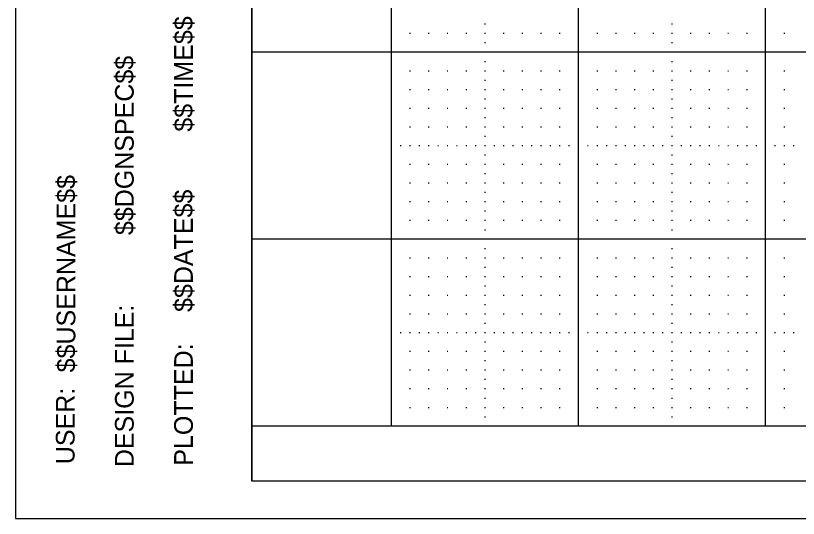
# Model space of a CAD drawing. Extents: x -1.3 to 32.1, y -0.2 to 20.7.
# Drawn here: x -1.263 to 2.92, y -0.2 to 2.487 of the extents above; entities that cross this region are included whole.
import ezdxf

# ---------------------------------------------------------------- set-up
doc = ezdxf.new("R2010")
doc.units = 0
for name, color, linetype in [('Level 1', 7, 'Continuous'), ('Level 37', 7, 'Continuous'), ('Level 5', 7, 'Continuous'), ('Level 6', 7, 'Continuous'), ('Level 62', 7, 'Continuous'), ('Level 63', 7, 'Continuous')]:
    doc.layers.add(name, color=color, linetype=linetype)

msp = doc.modelspace()

# ---------------------------------------------------------------- linework, layer by layer
at = {"layer": 'Level 1'}
for p, q in [((-0.001, -0.001), (-0.001, 20.545)), ((31.617, -0.001), (-0.001, -0.001))]:
    msp.add_line(p, q, dxfattribs=at)
at = {"layer": 'Level 37'}
for p, q in [((-0.001, 0.4818), (-0.001, 10.272)), ((-0.001, -0.001), (-0.001, 0.4818)), ((-0.001, 0.4818), (-0.001, 0.4818)), ((31.618, -0.001), (-0.001, -0.001))]:
    msp.add_line(p, q, dxfattribs=at)
at = {"layer": 'Level 5'}
for p, q in [((1.2425, 2.443), (1.2475, 2.443)), ((2.2425, 2.443), (2.2475, 2.443)), ((0.8425, 2.393), (0.8475, 2.393)), ((0.9425, 2.393), (0.9475, 2.393)), ((1.0425, 2.393), (1.0475, 2.393)), ((1.1425, 2.393), (1.1475, 2.393)), ((1.2425, 2.393), (1.2475, 2.393)), ((1.3425, 2.393), (1.3475, 2.393)), ((1.4425, 2.393), (1.4475, 2.393)), ((1.5425, 2.393), (1.5475, 2.393)), ((1.6425, 2.393), (1.6475, 2.393)), ((1.8425, 2.393), (1.8475, 2.393)), ((1.9425, 2.393), (1.9475, 2.393)), ((2.0425, 2.393), (2.0475, 2.393)), ((2.1425, 2.393), (2.1475, 2.393)), ((2.2425, 2.393), (2.2475, 2.393)), ((2.3425, 2.393), (2.3475, 2.393)), ((2.4425, 2.393), (2.4475, 2.393)), ((2.5425, 2.393), (2.5475, 2.393)), ((2.6425, 2.393), (2.6475, 2.393)), ((2.8425, 2.393), (2.8475, 2.393)), ((1.2425, 2.343), (1.2475, 2.343)), ((2.2425, 2.343), (2.2475, 2.343)), ((1.2425, 2.243), (1.2475, 2.243)), ((2.2425, 2.243), (2.2475, 2.243)), ((0.8425, 2.193), (0.8475, 2.193)), ((0.9425, 2.193), (0.9475, 2.193)), ((1.0425, 2.193), (1.0475, 2.193)), ((1.1425, 2.193), (1.1475, 2.193)), ((1.2425, 2.193), (1.2475, 2.193)), ((1.3425, 2.193), (1.3475, 2.193)), ((1.4425, 2.193), (1.4475, 2.193)), ((1.5425, 2.193), (1.5475, 2.193)), ((1.6425, 2.193), (1.6475, 2.193)), ((1.8425, 2.193), (1.8475, 2.193)), ((1.9425, 2.193), (1.9475, 2.193)), ((2.0425, 2.193), (2.0475, 2.193)), ((2.1425, 2.193), (2.1475, 2.193)), ((2.2425, 2.193), (2.2475, 2.193)), ((2.3425, 2.193), (2.3475, 2.193)), ((2.4425, 2.193), (2.4475, 2.193)), ((2.5425, 2.193), (2.5475, 2.193)), ((2.6425, 2.193), (2.6475, 2.193)), ((2.8425, 2.193), (2.8475, 2.193)), ((1.2425, 2.143), (1.2475, 2.143)), ((2.2425, 2.143), (2.2475, 2.143)), ((0.8425, 2.093), (0.8475, 2.093)), ((0.9425, 2.093), (0.9475, 2.093)), ((1.0425, 2.093), (1.0475, 2.093)), ((1.1425, 2.093), (1.1475, 2.093)), ((1.2425, 2.093), (1.2475, 2.093)), ((1.3425, 2.093), (1.3475, 2.093)), ((1.4425, 2.093), (1.4475, 2.093)), ((1.5425, 2.093), (1.5475, 2.093)), ((1.6425, 2.093), (1.6475, 2.093)), ((1.8425, 2.093), (1.8475, 2.093)), ((1.9425, 2.093), (1.9475, 2.093)), ((2.0425, 2.093), (2.0475, 2.093)), ((2.1425, 2.093), (2.1475, 2.093)), ((2.2425, 2.093), (2.2475, 2.093)), ((2.3425, 2.093), (2.3475, 2.093)), ((2.4425, 2.093), (2.4475, 2.093)), ((2.5425, 2.093), (2.5475, 2.093)), ((2.6425, 2.093), (2.6475, 2.093)), ((2.8425, 2.093), (2.8475, 2.093)), ((1.2425, 2.043), (1.2475, 2.043)), ((2.2425, 2.043), (2.2475, 2.043)), ((0.8425, 1.993), (0.8475, 1.993)), ((0.9425, 1.993), (0.9475, 1.993)), ((1.0425, 1.993), (1.0475, 1.993)), ((1.1425, 1.993), (1.1475, 1.993)), ((1.2425, 1.993), (1.2475, 1.993)), ((1.3425, 1.993), (1.3475, 1.993)), ((1.4425, 1.993), (1.4475, 1.993)), ((1.5425, 1.993), (1.5475, 1.993)), ((1.6425, 1.993), (1.6475, 1.993)), ((1.8425, 1.993), (1.8475, 1.993)), ((1.9425, 1.993), (1.9475, 1.993)), ((2.0425, 1.993), (2.0475, 1.993)), ((2.1425, 1.993), (2.1475, 1.993)), ((2.2425, 1.993), (2.2475, 1.993)), ((2.3425, 1.993), (2.3475, 1.993)), ((2.4425, 1.993), (2.4475, 1.993)), ((2.5425, 1.993), (2.5475, 1.993)), ((2.6425, 1.993), (2.6475, 1.993)), ((2.8425, 1.993), (2.8475, 1.993)), ((1.2425, 1.943), (1.2475, 1.943)), ((2.2425, 1.943), (2.2475, 1.943)), ((0.8425, 1.893), (0.8475, 1.893)), ((0.9425, 1.893), (0.9475, 1.893)), ((1.0425, 1.893), (1.0475, 1.893)), ((1.1425, 1.893), (1.1475, 1.893)), ((1.2425, 1.893), (1.2475, 1.893)), ((1.3425, 1.893), (1.3475, 1.893)), ((1.4425, 1.893), (1.4475, 1.893)), ((1.5425, 1.893), (1.5475, 1.893)), ((1.6425, 1.893), (1.6475, 1.893)), ((1.8425, 1.893), (1.8475, 1.893)), ((1.9425, 1.893), (1.9475, 1.893)), ((2.0425, 1.893), (2.0475, 1.893)), ((2.1425, 1.893), (2.1475, 1.893)), ((2.2425, 1.893), (2.2475, 1.893)), ((2.3425, 1.893), (2.3475, 1.893)), ((2.4425, 1.893), (2.4475, 1.893)), ((2.5425, 1.893), (2.5475, 1.893)), ((2.6425, 1.893), (2.6475, 1.893)), ((2.8425, 1.893), (2.8475, 1.893)), ((1.2425, 1.843), (1.2475, 1.843)), ((2.2425, 1.843), (2.2475, 1.843)), ((0.7925, 1.793), (0.7975, 1.793)), ((0.8425, 1.793), (0.8475, 1.793)), ((0.8925, 1.793), (0.8975, 1.793)), ((0.9425, 1.793), (0.9475, 1.793)), ((0.9925, 1.793), (0.9975, 1.793)), ((1.0425, 1.793), (1.0475, 1.793)), ((1.0925, 1.793), (1.0975, 1.793)), ((1.1425, 1.793), (1.1475, 1.793)), ((1.1925, 1.793), (1.1975, 1.793)), ((1.2425, 1.793), (1.2475, 1.793)), ((1.2925, 1.793), (1.2975, 1.793)), ((1.3425, 1.793), (1.3475, 1.793)), ((1.3925, 1.793), (1.3975, 1.793)), ((1.4425, 1.793), (1.4475, 1.793)), ((1.4925, 1.793), (1.4975, 1.793)), ((1.5425, 1.793), (1.5475, 1.793)), ((1.5925, 1.793), (1.5975, 1.793)), ((1.6425, 1.793), (1.6475, 1.793)), ((1.6925, 1.793), (1.6975, 1.793)), ((1.7925, 1.793), (1.7975, 1.793)), ((1.8425, 1.793), (1.8475, 1.793)), ((1.8925, 1.793), (1.8975, 1.793)), ((1.9425, 1.793), (1.9475, 1.793)), ((1.9925, 1.793), (1.9975, 1.793)), ((2.0425, 1.793), (2.0475, 1.793)), ((2.0925, 1.793), (2.0975, 1.793)), ((2.1425, 1.793), (2.1475, 1.793)), ((2.1925, 1.793), (2.1975, 1.793)), ((2.2425, 1.793), (2.2475, 1.793)), ((2.2925, 1.793), (2.2975, 1.793)), ((2.3425, 1.793), (2.3475, 1.793)), ((2.3925, 1.793), (2.3975, 1.793)), ((2.4425, 1.793), (2.4475, 1.793)), ((2.4925, 1.793), (2.4975, 1.793)), ((2.5425, 1.793), (2.5475, 1.793)), ((2.5925, 1.793), (2.5975, 1.793)), ((2.6425, 1.793), (2.6475, 1.793)), ((2.6925, 1.793), (2.6975, 1.793)), ((2.7925, 1.793), (2.7975, 1.793)), ((2.8425, 1.793), (2.8475, 1.793)), ((2.8925, 1.793), (2.8975, 1.793)), ((1.2425, 1.743), (1.2475, 1.743)), ((2.2425, 1.743), (2.2475, 1.743)), ((0.8425, 1.693), (0.8475, 1.693)), ((0.9425, 1.693), (0.9475, 1.693)), ((1.0425, 1.693), (1.0475, 1.693)), ((1.1425, 1.693), (1.1475, 1.693)), ((1.2425, 1.693), (1.2475, 1.693)), ((1.3425, 1.693), (1.3475, 1.693)), ((1.4425, 1.693), (1.4475, 1.693)), ((1.5425, 1.693), (1.5475, 1.693)), ((1.6425, 1.693), (1.6475, 1.693)), ((1.8425, 1.693), (1.8475, 1.693)), ((1.9425, 1.693), (1.9475, 1.693)), ((2.0425, 1.693), (2.0475, 1.693)), ((2.1425, 1.693), (2.1475, 1.693)), ((2.2425, 1.693), (2.2475, 1.693)), ((2.3425, 1.693), (2.3475, 1.693)), ((2.4425, 1.693), (2.4475, 1.693)), ((2.5425, 1.693), (2.5475, 1.693)), ((2.6425, 1.693), (2.6475, 1.693)), ((2.8425, 1.693), (2.8475, 1.693)), ((1.2425, 1.643), (1.2475, 1.643)), ((2.2425, 1.643), (2.2475, 1.643)), ((0.8425, 1.593), (0.8475, 1.593)), ((0.9425, 1.593), (0.9475, 1.593)), ((1.0425, 1.593), (1.0475, 1.593)), ((1.1425, 1.593), (1.1475, 1.593)), ((1.2425, 1.593), (1.2475, 1.593)), ((1.3425, 1.593), (1.3475, 1.593)), ((1.4425, 1.593), (1.4475, 1.593)), ((1.5425, 1.593), (1.5475, 1.593)), ((1.6425, 1.593), (1.6475, 1.593)), ((1.8425, 1.593), (1.8475, 1.593)), ((1.9425, 1.593), (1.9475, 1.593)), ((2.0425, 1.593), (2.0475, 1.593)), ((2.1425, 1.593), (2.1475, 1.593)), ((2.2425, 1.593), (2.2475, 1.593)), ((2.3425, 1.593), (2.3475, 1.593)), ((2.4425, 1.593), (2.4475, 1.593)), ((2.5425, 1.593), (2.5475, 1.593)), ((2.6425, 1.593), (2.6475, 1.593)), ((2.8425, 1.593), (2.8475, 1.593)), ((1.2425, 1.543), (1.2475, 1.543)), ((2.2425, 1.543), (2.2475, 1.543)), ((0.8425, 1.493), (0.8475, 1.493)), ((0.9425, 1.493), (0.9475, 1.493)), ((1.0425, 1.493), (1.0475, 1.493)), ((1.1425, 1.493), (1.1475, 1.493)), ((1.2425, 1.493), (1.2475, 1.493)), ((1.3425, 1.493), (1.3475, 1.493)), ((1.4425, 1.493), (1.4475, 1.493)), ((1.5425, 1.493), (1.5475, 1.493)), ((1.6425, 1.493), (1.6475, 1.493)), ((1.8425, 1.493), (1.8475, 1.493)), ((1.9425, 1.493), (1.9475, 1.493)), ((2.0425, 1.493), (2.0475, 1.493)), ((2.1425, 1.493), (2.1475, 1.493)), ((2.2425, 1.493), (2.2475, 1.493)), ((2.3425, 1.493), (2.3475, 1.493)), ((2.4425, 1.493), (2.4475, 1.493)), ((2.5425, 1.493), (2.5475, 1.493)), ((2.6425, 1.493), (2.6475, 1.493)), ((2.8425, 1.493), (2.8475, 1.493)), ((1.2425, 1.443), (1.2475, 1.443)), ((2.2425, 1.443), (2.2475, 1.443)), ((0.8425, 1.393), (0.8475, 1.393)), ((0.9425, 1.393), (0.9475, 1.393)), ((1.0425, 1.393), (1.0475, 1.393)), ((1.1425, 1.393), (1.1475, 1.393)), ((1.2425, 1.393), (1.2475, 1.393)), ((1.3425, 1.393), (1.3475, 1.393)), ((1.4425, 1.393), (1.4475, 1.393)), ((1.5425, 1.393), (1.5475, 1.393)), ((1.6425, 1.393), (1.6475, 1.393)), ((1.8425, 1.393), (1.8475, 1.393)), ((1.9425, 1.393), (1.9475, 1.393)), ((2.0425, 1.393), (2.0475, 1.393)), ((2.1425, 1.393), (2.1475, 1.393)), ((2.2425, 1.393), (2.2475, 1.393)), ((2.3425, 1.393), (2.3475, 1.393)), ((2.4425, 1.393), (2.4475, 1.393)), ((2.5425, 1.393), (2.5475, 1.393)), ((2.6425, 1.393), (2.6475, 1.393)), ((2.8425, 1.393), (2.8475, 1.393)), ((1.2425, 1.343), (1.2475, 1.343)), ((2.2425, 1.343), (2.2475, 1.343)), ((1.2425, 1.243), (1.2475, 1.243)), ((2.2425, 1.243), (2.2475, 1.243)), ((0.8425, 1.193), (0.8475, 1.193)), ((0.9425, 1.193), (0.9475, 1.193)), ((1.0425, 1.193), (1.0475, 1.193)), ((1.1425, 1.193), (1.1475, 1.193)), ((1.2425, 1.193), (1.2475, 1.193)), ((1.3425, 1.193), (1.3475, 1.193)), ((1.4425, 1.193), (1.4475, 1.193)), ((1.5425, 1.193), (1.5475, 1.193)), ((1.6425, 1.193), (1.6475, 1.193)), ((1.8425, 1.193), (1.8475, 1.193)), ((1.9425, 1.193), (1.9475, 1.193)), ((2.0425, 1.193), (2.0475, 1.193)), ((2.1425, 1.193), (2.1475, 1.193)), ((2.2425, 1.193), (2.2475, 1.193)), ((2.3425, 1.193), (2.3475, 1.193)), ((2.4425, 1.193), (2.4475, 1.193)), ((2.5425, 1.193), (2.5475, 1.193)), ((2.6425, 1.193), (2.6475, 1.193)), ((2.8425, 1.193), (2.8475, 1.193)), ((1.2425, 1.143), (1.2475, 1.143)), ((2.2425, 1.143), (2.2475, 1.143)), ((0.8425, 1.093), (0.8475, 1.093)), ((0.9425, 1.093), (0.9475, 1.093)), ((1.0425, 1.093), (1.0475, 1.093)), ((1.1425, 1.093), (1.1475, 1.093)), ((1.2425, 1.093), (1.2475, 1.093)), ((1.3425, 1.093), (1.3475, 1.093)), ((1.4425, 1.093), (1.4475, 1.093)), ((1.5425, 1.093), (1.5475, 1.093)), ((1.6425, 1.093), (1.6475, 1.093)), ((1.8425, 1.093), (1.8475, 1.093)), ((1.9425, 1.093), (1.9475, 1.093)), ((2.0425, 1.093), (2.0475, 1.093)), ((2.1425, 1.093), (2.1475, 1.093)), ((2.2425, 1.093), (2.2475, 1.093)), ((2.3425, 1.093), (2.3475, 1.093)), ((2.4425, 1.093), (2.4475, 1.093)), ((2.5425, 1.093), (2.5475, 1.093)), ((2.6425, 1.093), (2.6475, 1.093)), ((2.8425, 1.093), (2.8475, 1.093)), ((1.2425, 1.043), (1.2475, 1.043)), ((2.2425, 1.043), (2.2475, 1.043)), ((0.8425, 0.993), (0.8475, 0.993)), ((0.9425, 0.993), (0.9475, 0.993)), ((1.0425, 0.993), (1.0475, 0.993)), ((1.1425, 0.993), (1.1475, 0.993)), ((1.2425, 0.993), (1.2475, 0.993)), ((1.3425, 0.993), (1.3475, 0.993)), ((1.4425, 0.993), (1.4475, 0.993)), ((1.5425, 0.993), (1.5475, 0.993)), ((1.6425, 0.993), (1.6475, 0.993)), ((1.8425, 0.993), (1.8475, 0.993)), ((1.9425, 0.993), (1.9475, 0.993)), ((2.0425, 0.993), (2.0475, 0.993)), ((2.1425, 0.993), (2.1475, 0.993)), ((2.2425, 0.993), (2.2475, 0.993)), ((2.3425, 0.993), (2.3475, 0.993)), ((2.4425, 0.993), (2.4475, 0.993)), ((2.5425, 0.993), (2.5475, 0.993)), ((2.6425, 0.993), (2.6475, 0.993)), ((2.8425, 0.993), (2.8475, 0.993)), ((1.2425, 0.943), (1.2475, 0.943)), ((2.2425, 0.943), (2.2475, 0.943)), ((0.8425, 0.893), (0.8475, 0.893)), ((0.9425, 0.893), (0.9475, 0.893)), ((1.0425, 0.893), (1.0475, 0.893)), ((1.1425, 0.893), (1.1475, 0.893)), ((1.2425, 0.893), (1.2475, 0.893)), ((1.3425, 0.893), (1.3475, 0.893)), ((1.4425, 0.893), (1.4475, 0.893)), ((1.5425, 0.893), (1.5475, 0.893)), ((1.6425, 0.893), (1.6475, 0.893)), ((1.8425, 0.893), (1.8475, 0.893)), ((1.9425, 0.893), (1.9475, 0.893)), ((2.0425, 0.893), (2.0475, 0.893)), ((2.1425, 0.893), (2.1475, 0.893)), ((2.2425, 0.893), (2.2475, 0.893)), ((2.3425, 0.893), (2.3475, 0.893)), ((2.4425, 0.893), (2.4475, 0.893)), ((2.5425, 0.893), (2.5475, 0.893)), ((2.6425, 0.893), (2.6475, 0.893)), ((2.8425, 0.893), (2.8475, 0.893)), ((1.2425, 0.843), (1.2475, 0.843)), ((2.2425, 0.843), (2.2475, 0.843)), ((0.7925, 0.793), (0.7975, 0.793)), ((0.8425, 0.793), (0.8475, 0.793)), ((0.8925, 0.793), (0.8975, 0.793)), ((0.9425, 0.793), (0.9475, 0.793)), ((0.9925, 0.793), (0.9975, 0.793)), ((1.0425, 0.793), (1.0475, 0.793)), ((1.0925, 0.793), (1.0975, 0.793)), ((1.1425, 0.793), (1.1475, 0.793)), ((1.1925, 0.793), (1.1975, 0.793)), ((1.2425, 0.793), (1.2475, 0.793)), ((1.2925, 0.793), (1.2975, 0.793)), ((1.3425, 0.793), (1.3475, 0.793)), ((1.3925, 0.793), (1.3975, 0.793)), ((1.4425, 0.793), (1.4475, 0.793)), ((1.4925, 0.793), (1.4975, 0.793)), ((1.5425, 0.793), (1.5475, 0.793)), ((1.5925, 0.793), (1.5975, 0.793)), ((1.6425, 0.793), (1.6475, 0.793)), ((1.6925, 0.793), (1.6975, 0.793)), ((1.7925, 0.793), (1.7975, 0.793)), ((1.8425, 0.793), (1.8475, 0.793)), ((1.8925, 0.793), (1.8975, 0.793)), ((1.9425, 0.793), (1.9475, 0.793)), ((1.9925, 0.793), (1.9975, 0.793)), ((2.0425, 0.793), (2.0475, 0.793)), ((2.0925, 0.793), (2.0975, 0.793)), ((2.1425, 0.793), (2.1475, 0.793)), ((2.1925, 0.793), (2.1975, 0.793)), ((2.2425, 0.793), (2.2475, 0.793)), ((2.2925, 0.793), (2.2975, 0.793)), ((2.3425, 0.793), (2.3475, 0.793)), ((2.3925, 0.793), (2.3975, 0.793)), ((2.4425, 0.793), (2.4475, 0.793)), ((2.4925, 0.793), (2.4975, 0.793)), ((2.5425, 0.793), (2.5475, 0.793)), ((2.5925, 0.793), (2.5975, 0.793)), ((2.6425, 0.793), (2.6475, 0.793)), ((2.6925, 0.793), (2.6975, 0.793)), ((2.7925, 0.793), (2.7975, 0.793)), ((2.8425, 0.793), (2.8475, 0.793)), ((2.8925, 0.793), (2.8975, 0.793)), ((1.2425, 0.743), (1.2475, 0.743)), ((2.2425, 0.743), (2.2475, 0.743)), ((0.8425, 0.693), (0.8475, 0.693)), ((0.9425, 0.693), (0.9475, 0.693)), ((1.0425, 0.693), (1.0475, 0.693)), ((1.1425, 0.693), (1.1475, 0.693)), ((1.2425, 0.693), (1.2475, 0.693)), ((1.3425, 0.693), (1.3475, 0.693)), ((1.4425, 0.693), (1.4475, 0.693)), ((1.5425, 0.693), (1.5475, 0.693)), ((1.6425, 0.693), (1.6475, 0.693)), ((1.8425, 0.693), (1.8475, 0.693)), ((1.9425, 0.693), (1.9475, 0.693)), ((2.0425, 0.693), (2.0475, 0.693)), ((2.1425, 0.693), (2.1475, 0.693)), ((2.2425, 0.693), (2.2475, 0.693)), ((2.3425, 0.693), (2.3475, 0.693)), ((2.4425, 0.693), (2.4475, 0.693)), ((2.5425, 0.693), (2.5475, 0.693)), ((2.6425, 0.693), (2.6475, 0.693)), ((2.8425, 0.693), (2.8475, 0.693)), ((1.2425, 0.643), (1.2475, 0.643)), ((2.2425, 0.643), (2.2475, 0.643)), ((0.8425, 0.593), (0.8475, 0.593)), ((0.9425, 0.593), (0.9475, 0.593)), ((1.0425, 0.593), (1.0475, 0.593)), ((1.1425, 0.593), (1.1475, 0.593)), ((1.2425, 0.593), (1.2475, 0.593)), ((1.3425, 0.593), (1.3475, 0.593)), ((1.4425, 0.593), (1.4475, 0.593)), ((1.5425, 0.593), (1.5475, 0.593)), ((1.6425, 0.593), (1.6475, 0.593)), ((1.8425, 0.593), (1.8475, 0.593)), ((1.9425, 0.593), (1.9475, 0.593)), ((2.0425, 0.593), (2.0475, 0.593)), ((2.1425, 0.593), (2.1475, 0.593)), ((2.2425, 0.593), (2.2475, 0.593)), ((2.3425, 0.593), (2.3475, 0.593)), ((2.4425, 0.593), (2.4475, 0.593)), ((2.5425, 0.593), (2.5475, 0.593)), ((2.6425, 0.593), (2.6475, 0.593)), ((2.8425, 0.593), (2.8475, 0.593)), ((1.2425, 0.543), (1.2475, 0.543)), ((2.2425, 0.543), (2.2475, 0.543)), ((0.8425, 0.493), (0.8475, 0.493)), ((0.9425, 0.493), (0.9475, 0.493)), ((1.0425, 0.493), (1.0475, 0.493)), ((1.1425, 0.493), (1.1475, 0.493)), ((1.2425, 0.493), (1.2475, 0.493)), ((1.3425, 0.493), (1.3475, 0.493)), ((1.4425, 0.493), (1.4475, 0.493)), ((1.5425, 0.493), (1.5475, 0.493)), ((1.6425, 0.493), (1.6475, 0.493)), ((1.8425, 0.493), (1.8475, 0.493)), ((1.9425, 0.493), (1.9475, 0.493)), ((2.0425, 0.493), (2.0475, 0.493)), ((2.1425, 0.493), (2.1475, 0.493)), ((2.2425, 0.493), (2.2475, 0.493)), ((2.3425, 0.493), (2.3475, 0.493)), ((2.4425, 0.493), (2.4475, 0.493)), ((2.5425, 0.493), (2.5475, 0.493)), ((2.6425, 0.493), (2.6475, 0.493)), ((2.8425, 0.493), (2.8475, 0.493)), ((1.2425, 0.443), (1.2475, 0.443)), ((2.2425, 0.443), (2.2475, 0.443)), ((0.8425, 0.393), (0.8475, 0.393)), ((0.9425, 0.393), (0.9475, 0.393)), ((1.0425, 0.393), (1.0475, 0.393)), ((1.1425, 0.393), (1.1475, 0.393)), ((1.2425, 0.393), (1.2475, 0.393)), ((1.3425, 0.393), (1.3475, 0.393)), ((1.4425, 0.393), (1.4475, 0.393)), ((1.5425, 0.393), (1.5475, 0.393)), ((1.6425, 0.393), (1.6475, 0.393)), ((1.8425, 0.393), (1.8475, 0.393)), ((1.9425, 0.393), (1.9475, 0.393)), ((2.0425, 0.393), (2.0475, 0.393)), ((2.1425, 0.393), (2.1475, 0.393)), ((2.2425, 0.393), (2.2475, 0.393)), ((2.3425, 0.393), (2.3475, 0.393)), ((2.4425, 0.393), (2.4475, 0.393)), ((2.5425, 0.393), (2.5475, 0.393)), ((2.6425, 0.393), (2.6475, 0.393)), ((2.8425, 0.393), (2.8475, 0.393)), ((1.2425, 0.343), (1.2475, 0.343)), ((2.2425, 0.343), (2.2475, 0.343))]:
    msp.add_line(p, q, dxfattribs=at)
at = {"layer": 'Level 6'}
for p, q in [((0.745, 0.293), (0.745, 10.293)), ((1.745, 0.293), (1.745, 10.293)), ((2.745, 0.293), (2.745, 10.293)), ((31.617, 2.293), (-0.001, 2.293)), ((31.617, 1.293), (-0.001, 1.293)), ((31.617, 0.293), (-0.001, 0.293))]:
    msp.add_line(p, q, dxfattribs=at)
at = {"layer": 'Level 62'}
for p, q in [((0, 10.294), (0, -0.001)), ((-0.001, -0.001), (-0.001, 0)), ((-0.001, 0), (31.618, 0)), ((0, -0.001), (-0.001, -0.001))]:
    msp.add_line(p, q, dxfattribs=at)
at = {"layer": 'Level 63'}
msp.add_lwpolyline([(-1.263, -0.2005), (32.067, -0.2005), (32.067, 20.7465), (-1.263, 20.7465)], close=True, dxfattribs=at)

# ---------------------------------------------------------------- texts
at = {"layer": 'Level 1'}
for s, height, p in [('$$TIME$$', 0.1, (-0.316, 1.867)), ('$$DGNSPEC$$', 0.100002, (-0.632, 1.314)), ('$$USERNAME$$', 0.100002, (-0.944, 0.58)), ('$$DATE$$', 0.1, (-0.316, 0.903)), ('DESIGN FILE:', 0.100002, (-0.632, 0.073)), ('PLOTTED:', 0.1, (-0.316, 0.081)), ('USER:', 0.1, (-0.948, 0.089))]:
    msp.add_text(s, height=height, rotation=90, dxfattribs=at).set_placement(p)

doc.saveas('drawing.dxf')
